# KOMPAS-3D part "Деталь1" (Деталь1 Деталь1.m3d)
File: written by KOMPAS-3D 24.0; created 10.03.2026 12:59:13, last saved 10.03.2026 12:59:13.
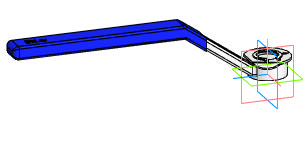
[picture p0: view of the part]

Document properties: Автор: R2D2; Полное имя файла: E:\Работа\Зайцев\BV3232P(4pc)-FP-3WL-F-ISO-H Кран шаровой DN.ru Ду15-100 Ру16\DN65\исходные материалы\Деталь1 Деталь1.m3d

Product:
- Body: Твердое тело1  | qty 1
- Part/product: Деталь1
    additional columns: Типовые

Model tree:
1. Твердое тело1  (labels: Твердое тело1)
